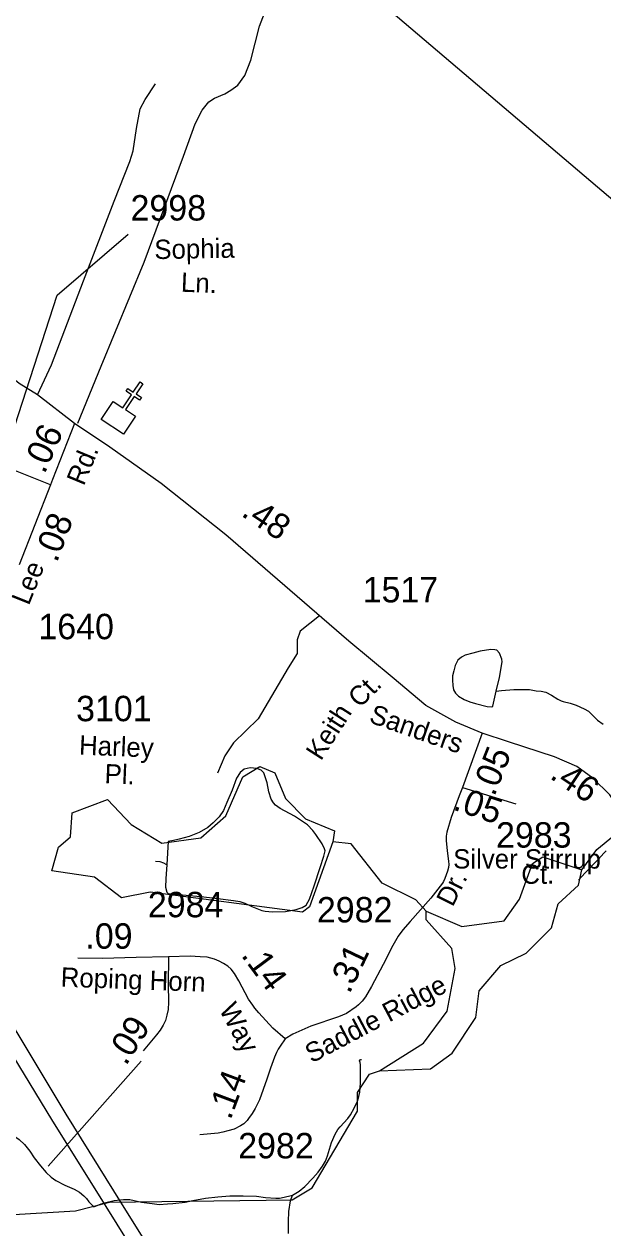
# Model space of a CAD drawing. Extents: x 2082433 to 2279600, y 546599 to 755198.
# Drawn here: x 2126324 to 2129173, y 651046 to 656969 of the extents above; entities that cross this region are included whole.
import ezdxf

# ---------------------------------------------------------------- set-up
doc = ezdxf.new("R2010")
doc.units = 0
for name, color, linetype in [('Exist Boundary Political Fire Districts', 7, 'Continuous'), ('Exist Cultural Church CELL', 7, 'Continuous'), ('Exist Hydrographic Creek Single Shore', 7, 'Continuous'), ('Exist Hydrographic Lake Shore', 7, 'Continuous'), ('Exist Hydrographic Misc Water Feature', 7, 'Continuous'), ('Exist Hydrographic Pond Under 1500 Sq Ft', 7, 'Continuous'), ('Exist Road Non-System Type 51', 7, 'Continuous'), ('Exist Road Non-System Type 51 Label', 7, 'Continuous'), ('Exist Road Primary Interstate Divided Center Attributed', 7, 'Continuous'), ('Exist Road Secondary Mileage Hundredths English Label', 7, 'Continuous'), ('Exist Road Secondary Type 51 Attributed', 7, 'Continuous'), ('Exist Road Secondary Type 51 Label', 7, 'Continuous'), ('Exist Road Secondary Type 51 Number Label', 7, 'Continuous')]:
    doc.layers.add(name, color=color, linetype=linetype)

msp = doc.modelspace()

# ---------------------------------------------------------------- linework, layer by layer
at = {"layer": 'Exist Boundary Political Fire Districts'}
msp.add_lwpolyline([(2126117, 658742.4), (2137007.1, 649490.6)], dxfattribs=at)
at = {"layer": 'Exist Cultural Church CELL'}
msp.add_lwpolyline([(2126763.2, 655112.7), (2126810.7, 655081.3), (2126852.9, 655144.7), (2126826.2, 655162.4), (2126835.1, 655175.7), (2126861.7, 655158), (2126895, 655208.1), (2126908.4, 655199.2), (2126875.1, 655149.1), (2126901.7, 655131.4), (2126892.9, 655118.1), (2126866.2, 655135.8), (2126824.1, 655072.4), (2126872, 655040.4), (2126813.1, 654951.7), (2126704.3, 655024.1)], close=True, dxfattribs=at)
at = {"layer": 'Exist Hydrographic Creek Single Shore'}
for points in [[(2129069.1, 652808.4), (2129144.2, 652908.5), (2129500.2, 653199.8), (2129672.2, 653924.5), (2129671.2, 654167.3), (2129736.2, 654602.2), (2129743.2, 654867.8), (2129842.2, 655102), (2129850.2, 655210.1), (2129949.3, 655385.2), (2130306.3, 655686.4), (2130430.1, 655861), (2130613.2, 655972), (2130837.2, 656072.5), (2130887.2, 656163.3)], [(2125017.1, 651696.6), (2125018.1, 651430.9), (2124993.1, 651388.7), (2124986.1, 651064.1), (2125137, 650880.6), (2125262.1, 650842), (2125545.1, 650901.9), (2125660.9, 650958.5), (2125803, 651083.6), (2126577.1, 651130.2), (2126744, 651172.8), (2127643, 651184), (2127743, 651244.2), (2127966.1, 651620.2), (2127966.1, 651712.1), (2128024, 651802.8), (2128074, 651818.2)]]:
    msp.add_lwpolyline(points, dxfattribs=at)
at = {"layer": 'Exist Hydrographic Lake Shore'}
for points in [[(2128304.1, 652604.1), (2128479, 652528.4), (2128687.1, 652556.9), (2128762.2, 652663.6), (2128827.2, 652839.5), (2128877, 652871.3), (2129069.1, 652808.4)], [(2128074, 651818.2), (2128324, 651829.5), (2128432, 651906), (2128548.1, 652080.9), (2128564.1, 652211.8), (2128671.1, 652337.5), (2128796, 652397.3), (2128920.1, 652522.7), (2128953.1, 652640.1), (2129053.1, 652733.2), (2129069.1, 652808.4)], [(2128074, 651818.2), (2128290.1, 651954.9), (2128406, 652113.2), (2128446, 652322.3), (2128429.2, 652421.1), (2128304.1, 652561.5), (2128304.1, 652604.1)]]:
    msp.add_lwpolyline(points, dxfattribs=at)
at = {"layer": 'Exist Hydrographic Misc Water Feature'}
for points in [[(2128647.9, 653686.7), (2128663.5, 653754.5), (2128677.1, 653830.7), (2128675, 653844.4), (2128664.7, 653874.3), (2128651, 653888.6), (2128640.6, 653890.6), (2128620.9, 653892.3), (2128569, 653884), (2128533.3, 653874), (2128495, 653863.9), (2128477.1, 653853.6), (2128459.1, 653839.7), (2128445.3, 653813.4), (2128439.4, 653787.6), (2128433.4, 653761.7), (2128433.4, 653741.5), (2128433.9, 653715.4), (2128437.8, 653693.7), (2128447.8, 653677.6), (2128461.7, 653661.7), (2128490, 653645.7), (2128517.9, 653634.1), (2128546, 653626.3), (2128604.1, 653612.2), (2128625.8, 653610.5), (2128632.1, 653612.4), (2128647.9, 653686.7)], [(2128647.9, 653686.7), (2128673.6, 653690.5), (2128735.5, 653694.9), (2128769.5, 653695), (2128811.6, 653695.2), (2128845.6, 653689.2), (2128869.8, 653687.6), (2128891.9, 653681.8), (2128919.6, 653667.9), (2128951.6, 653648), (2128967.8, 653639.9), (2128977.7, 653636), (2129011.7, 653628), (2129041.8, 653618.1), (2129081.8, 653600.3), (2129102.1, 653588.8), (2129115.9, 653574.5), (2129146.2, 653544.8), (2129174.3, 653524.7)], [(2127760.9, 652980.9), (2127745.1, 653000.8), (2127718.8, 653028.7), (2127690.5, 653048.3), (2127655.1, 653072.4), (2127584.5, 653110.3), (2127562.4, 653126.2), (2127552.5, 653137.8), (2127540.2, 653155.9), (2127528.3, 653191.8), (2127519.9, 653235.6), (2127503.5, 653285.5), (2127491.8, 653297.4), (2127469.9, 653305.6), (2127437.7, 653309.3), (2127408, 653303.3), (2127387.9, 653287.2), (2127369.8, 653259.1), (2127348.5, 653199.1), (2127322.3, 653139), (2127305, 653099), (2127284.7, 653068.8), (2127255, 653038.9), (2127228.8, 653016.5), (2127185.3, 652992.2), (2127137.3, 652972.3), (2127087.3, 652958), (2127059.6, 652952), (2127033.8, 652947.8), (2127026.2, 652833.8)], [(2127026.2, 652833.8), (2127022.3, 652763.8), (2127020.2, 652721.9), (2127026.6, 652697.9), (2127032.7, 652691.6), (2127068.6, 652687.8), (2127140.8, 652682.2), (2127208.3, 652674.4), (2127278.6, 652667), (2127354.7, 652657.1), (2127386.5, 652651.5), (2127411.1, 652643.3), (2127444.5, 652627.7), (2127494.7, 652607.9), (2127510.7, 652603.9), (2127547, 652602), (2127610.8, 652602.1), (2127662.7, 652612.6), (2127692.8, 652622.6), (2127712.7, 652634.6), (2127728.5, 652663), (2127752.1, 652728.8), (2127782, 652818.8), (2127799.4, 652874.9), (2127805.4, 652901.2), (2127803.3, 652911.3), (2127791.2, 652935), (2127760.9, 652980.9)], [(2128304.1, 652604.1), (2128253, 652660.9), (2128086.1, 652743), (2127935, 652936.4), (2127844.1, 652944.8)], [(2129053.9, 652756.5), (2129085.5, 652792.7), (2129151.3, 652861), (2129177.2, 652889.1), (2129188.9, 652901.1)], [(2126971.8, 652851.3), (2126991.9, 652849.5), (2127010, 652841.5), (2127022.3, 652835.6), (2127026.2, 652833.8)], [(2127644.8, 651207.1), (2127678.7, 651227.1), (2127706.5, 651249.2), (2127746.3, 651291.5), (2127772.2, 651321.2), (2127792.3, 651349.4), (2127808, 651375.4), (2127818.3, 651401.5), (2127838, 651465.8), (2127855.6, 651507.8), (2127869.3, 651530), (2127879.4, 651543.9), (2127917.5, 651584), (2127931.3, 651602.2), (2127948.7, 651636), (2127964.7, 651670.1), (2127972.5, 651692.4), (2127976.6, 651714.1), (2127980.5, 651760.2), (2127980.5, 651806), (2127980.3, 651830.4), (2127980.3, 651848.2), (2127978, 651860.3), (2127976, 651868), (2127979.5, 651874.3), (2127985.8, 651874.2)], [(2126059.6, 651575.9), (2126079.7, 651553.8), (2126095.4, 651544.1), (2126119.8, 651531.9), (2126159.8, 651522.2), (2126219.9, 651514.8), (2126255.8, 651508.9), (2126278.1, 651496.6), (2126300.1, 651480.7), (2126326.3, 651456.9), (2126352, 651423), (2126374.3, 651391.2), (2126404.3, 651351.4), (2126432.5, 651319.5), (2126456.7, 651295.6), (2126480.7, 651279.8), (2126524.8, 651256.1), (2126570.8, 651236.1), (2126597, 651222), (2126619.1, 651204.5), (2126631.2, 651190.5), (2126643.1, 651174.5), (2126659.5, 651158.6), (2126667.5, 651150.5)], [(2126667.5, 651150.5), (2126703, 651164.6), (2126741.4, 651175.1), (2126767.4, 651180.9), (2126813.1, 651185.3), (2126845.5, 651185.3), (2126902.9, 651173.7), (2126955.2, 651165.8), (2126989.1, 651161.9), (2127029.5, 651164.3), (2127056.9, 651166.3), (2127117, 651172.6), (2127154.9, 651180.6), (2127216.9, 651193.1), (2127277.2, 651199.4), (2127336.8, 651203.4), (2127403.3, 651203.9), (2127468.9, 651202), (2127513, 651196.2), (2127562.8, 651192.7), (2127581.3, 651192.8), (2127605.2, 651196.8), (2127638.9, 651205.1), (2127644.8, 651207.1)], [(2127625.7, 651018.9), (2127625.5, 651077), (2127627.2, 651127), (2127635, 651178.9), (2127644.8, 651207.1)]]:
    msp.add_lwpolyline(points, dxfattribs=at)
at = {"layer": 'Exist Hydrographic Pond Under 1500 Sq Ft'}
msp.add_lwpolyline([(2127844.1, 652944.8), (2127729.1, 652625.6), (2127695.1, 652600), (2126945, 652697.4), (2126804.1, 652670.7), (2126670, 652771.8), (2126461.1, 652802.3), (2126494.1, 652919.7), (2126552.1, 652971), (2126560.1, 653089), (2126735, 653154.3), (2126852.1, 653030.5), (2127002, 652938.9), (2127194.1, 652964.5), (2127318, 653073.5), (2127401, 653265.4), (2127484.1, 653316.2), (2127559.1, 653285.1), (2127610.2, 653159.4), (2127710, 653059), (2127852.2, 653000.3), (2127844.1, 652944.8)], dxfattribs=at)
at = {"layer": 'Exist Road Non-System Type 51'}
for points in [[(2126588.1, 655004.6), (2126703.5, 655285.3), (2126915.5, 655797), (2127108.4, 656318.9), (2127165.5, 656477.7), (2127201, 656545), (2127234, 656586.9), (2127261.9, 656604.7), (2127312.7, 656625), (2127341.9, 656642.8), (2127376.1, 656668.2), (2127410.4, 656715.1), (2127440.8, 656791.3), (2127482.7, 656957.7), (2127524.6, 657064.4), (2127544.9, 657105), (2127553.8, 657144.4), (2127552.5, 657192.6), (2127539.8, 657256.1), (2127536, 657319.6)], [(2126390.1, 655144.3), (2126458.6, 655292.9), (2126617.3, 655705.6), (2126768.3, 656098), (2126844.4, 656292.3), (2126860.9, 656344.3), (2126877.4, 656454.8), (2126895.2, 656551.3), (2126920.5, 656597), (2126971.3, 656674.5)], [(2127777.9, 654057.8), (2127683.1, 653982.6), (2127669, 653940.1), (2127667.6, 653872.1), (2127623.7, 653801.3), (2127476.5, 653550.6), (2127355.5, 653433.1), (2127311.6, 653369.4), (2127276.2, 653283)]]:
    msp.add_lwpolyline(points, dxfattribs=at)
at = {"layer": 'Exist Road Primary Interstate Divided Center Attributed'}
for points in [[(2125101, 656322.4), (2125024.2, 656126.3), (2124962, 655968.5), (2124910.1, 655781.7), (2124862.3, 655563.8), (2124833.3, 655374.9), (2124828, 655244.1), (2124816.7, 655028.2), (2124827.1, 654895.4), (2124870.6, 654507.2), (2124926.7, 654285.1), (2125015.9, 654017.3), (2125096.9, 653820.2), (2125175.8, 653666.5), (2125353.2, 653369.4), (2125702.8, 652816.1), (2126026.8, 652290.3), (2126459.2, 651579.4), (2126726.2, 651152), (2127508.6, 649894.7), (2127823.3, 649376.4), (2128125.3, 648890.4)], [(2128205.4, 648915.7), (2127922.6, 649387.5), (2127681.4, 649762.7), (2126803.4, 651167.7), (2126530.8, 651605.2), (2126043.4, 652414.9), (2125377.1, 653477.7), (2125198.6, 653789), (2125103.1, 653998.7), (2125020.1, 654233.2), (2124943.3, 654509.3), (2124908, 654764.6), (2124897.6, 654988.8), (2124897.6, 655200.5), (2124916.3, 655443.4), (2124966.1, 655700.8), (2125013.9, 655868.9), (2125077.2, 656048.4), (2125161.2, 656261.2)]]:
    msp.add_lwpolyline(points, dxfattribs=at)
at = {"layer": 'Exist Road Secondary Type 51 Attributed'}
msp.add_line((2128482.5, 653212.9), (2128744.8, 653131.8), dxfattribs=at)
for points in [[(2126572.3, 655003.3), (2126390.1, 655144.3), (2126300.8, 655200.8), (2126087, 655370.7), (2125869.8, 655595.1), (2125624.1, 655831.5), (2125161.2, 656261.2)], [(2126572.3, 655003.3), (2126463.9, 654727.8), (2126454.2, 654702.6)], [(2128579, 653480.5), (2128449.1, 653533.5), (2128301.1, 653616.3), (2128135.6, 653756.5), (2127922.3, 653933.2), (2127316.9, 654455.5), (2126999.4, 654708.7), (2126746.4, 654887.1), (2126572.3, 655003.3)], [(2126454.2, 654702.6), (2126190.8, 654806.6), (2126163.6, 654833.8)], [(2126454.2, 654702.6), (2126299.9, 654308.6)], [(2128579, 653480.5), (2128482.5, 653212.9)], [(2130239.5, 651839), (2130123.9, 651887.3), (2130056.6, 651933.9), (2129880.7, 652159.9), (2129724.5, 652371.1), (2129373.6, 652936.4), (2129207.3, 653176.8), (2129124.5, 653258.1), (2129045, 653317), (2128935.2, 653363.2), (2128709.2, 653438), (2128579, 653480.5)], [(2128482.5, 653212.9), (2128466.3, 653172.4), (2128427.2, 653065.3), (2128404.4, 652993), (2128401.1, 652973.1), (2128401.6, 652952.6), (2128406.7, 652901.6), (2128413.8, 652850.9), (2128414.6, 652834.7), (2128413, 652819.3), (2128408.3, 652800.6), (2128395.3, 652764.9), (2128389, 652751.1), (2128384, 652741.9), (2128326.2, 652667.9), (2128223.9, 652553.6), (2128188.5, 652512.4), (2128165.8, 652481.2), (2128138.5, 652435.8), (2128091.6, 652342.9), (2128034.5, 652233.9), (2128005.2, 652183.8), (2127988.5, 652162.1), (2127970.2, 652142.9), (2127959.3, 652133.7), (2127910.4, 652101.2), (2127872.2, 652085.3), (2127735.8, 652039.1), (2127646.4, 651999.9), (2127609, 651976.8)], [(2127034.5, 652380.3), (2126876.3, 652376.3), (2126710.4, 652372.2), (2126589.4, 652373.6)], [(2127034.5, 652380.3), (2127033.2, 652244), (2127035.6, 652157), (2127033.6, 652120.9), (2127026.9, 652093), (2127019.5, 652066.6), (2127009, 652044), (2126993.8, 652019.4), (2126976.8, 651996.4), (2126909.9, 651917.7)], [(2127609, 651976.8), (2127548.4, 652029.5), (2127479.3, 652105), (2127460.4, 652127.5), (2127450, 652142), (2127429.6, 652171.8), (2127381.4, 652262.5), (2127360.6, 652297.3), (2127343.1, 652319.3), (2127326.4, 652334.3), (2127306.1, 652346.9), (2127284.4, 652358.7), (2127262.2, 652368.2), (2127224.7, 652378.1), (2127190.3, 652380.4), (2127142.1, 652382.6), (2127034.5, 652380.3)], [(2127609, 651976.8), (2127584, 651939.8), (2127575.6, 651925.2), (2127566.9, 651908.9), (2127556.8, 651885.9), (2127537.1, 651831.9), (2127518.7, 651777.6), (2127482.6, 651676.7), (2127461.3, 651633.9), (2127446.2, 651609.5), (2127429.3, 651584.3), (2127422, 651575.3), (2127405.1, 651558.5), (2127389.7, 651548.5), (2127357.6, 651532.7), (2127327.8, 651523.2), (2127302.2, 651517.4), (2127280, 651512.4), (2127189.2, 651504.2)]]:
    msp.add_lwpolyline(points, dxfattribs=at)
at = {"layer": 'Exist Road Secondary Type 51 Number Label'}
msp.add_line((2126900.9, 651867.1), (2126442.9, 651349.9), dxfattribs=at)
msp.add_lwpolyline([(2126240.9, 654876.1), (2126487.2, 655634.6), (2126836.9, 655935)], dxfattribs=at)

# ---------------------------------------------------------------- texts
at = {"layer": 'Exist Road Non-System Type 51 Label'}
for s, rotation, p in [('Ct.', 44.78511, (2127976.2, 653600.5)), ('Keith', 57.2834, (2127785.3, 653340.3))]:
    msp.add_text(s, height=95, rotation=rotation, dxfattribs=at).set_placement(p)
at = {"layer": 'Exist Road Secondary Mileage Hundredths English Label'}
for s, rotation, p in [('.06', 65.84668, (2126424.5, 654751.3)), ('.08', 69.10698, (2126485.3, 654315.5)), ('.48', 326.26729, (2127387.8, 654552.2)), ('.05', 68.36558, (2128638.7, 653164.9)), ('.46', 326.26729, (2128906.7, 653260.8)), ('.05', 341.21317, (2128430.6, 653105.3)), ('.09', 0.00002, (2126625.8, 652419.8)), ('.14', 306.5768, (2127389.4, 652386.9)), ('.31', 64.45139, (2127925.8, 652193.6)), ('.09', 57.6659, (2126825.4, 651840.1)), ('.14', 69.45346, (2127340.1, 651573.4))]:
    msp.add_text(s, height=125, rotation=rotation, dxfattribs=at).set_placement(p)
at = {"layer": 'Exist Road Secondary Type 51 Label'}
for s, rotation, p in [('Sophia', 1.00896, (2126966.1, 655812.3)), ('Ln.', 357.64091, (2127095, 655652.2)), ('Rd.', 67.45528, (2126617.8, 654693.1)), ('Lee', 68.21033, (2126347.4, 654104.8)), ('Sanders', 340.76754, (2128017.4, 653534.7)), ('Harley', 357.64091, (2126593.4, 653375)), ('Pl.', 357.64091, (2126719, 653234)), ('Silver Stirrup', 359.95409, (2128436.2, 652814.4)), ('Ct.', 359.95409, (2128771.6, 652739.1)), ('Dr.', 63.44651, (2128433.8, 652621.2)), ('Roping Horn', 357.9203, (2126503.3, 652233.4)), ('Saddle Ridge', 27.90926, (2127739.7, 651854.8)), ('Way', 298.28868, (2127281.8, 652121.6))]:
    msp.add_text(s, height=95, rotation=rotation, dxfattribs=at).set_placement(p)
at = {"layer": 'Exist Road Secondary Type 51 Number Label'}
for s, p in [('2998', (2126848.2, 656002.2)), ('1517', (2127990.7, 654123.6)), ('1640', (2126394.6, 653942.3)), ('3101', (2126580.1, 653539)), ('2983', (2128647.3, 652917.1)), ('2984', (2126933.4, 652574.5)), ('2982', (2127765.5, 652549.1)), ('2982', (2127378.1, 651388.4))]:
    msp.add_text(s, height=125, dxfattribs=at).set_placement(p)

doc.saveas('drawing.dxf')
